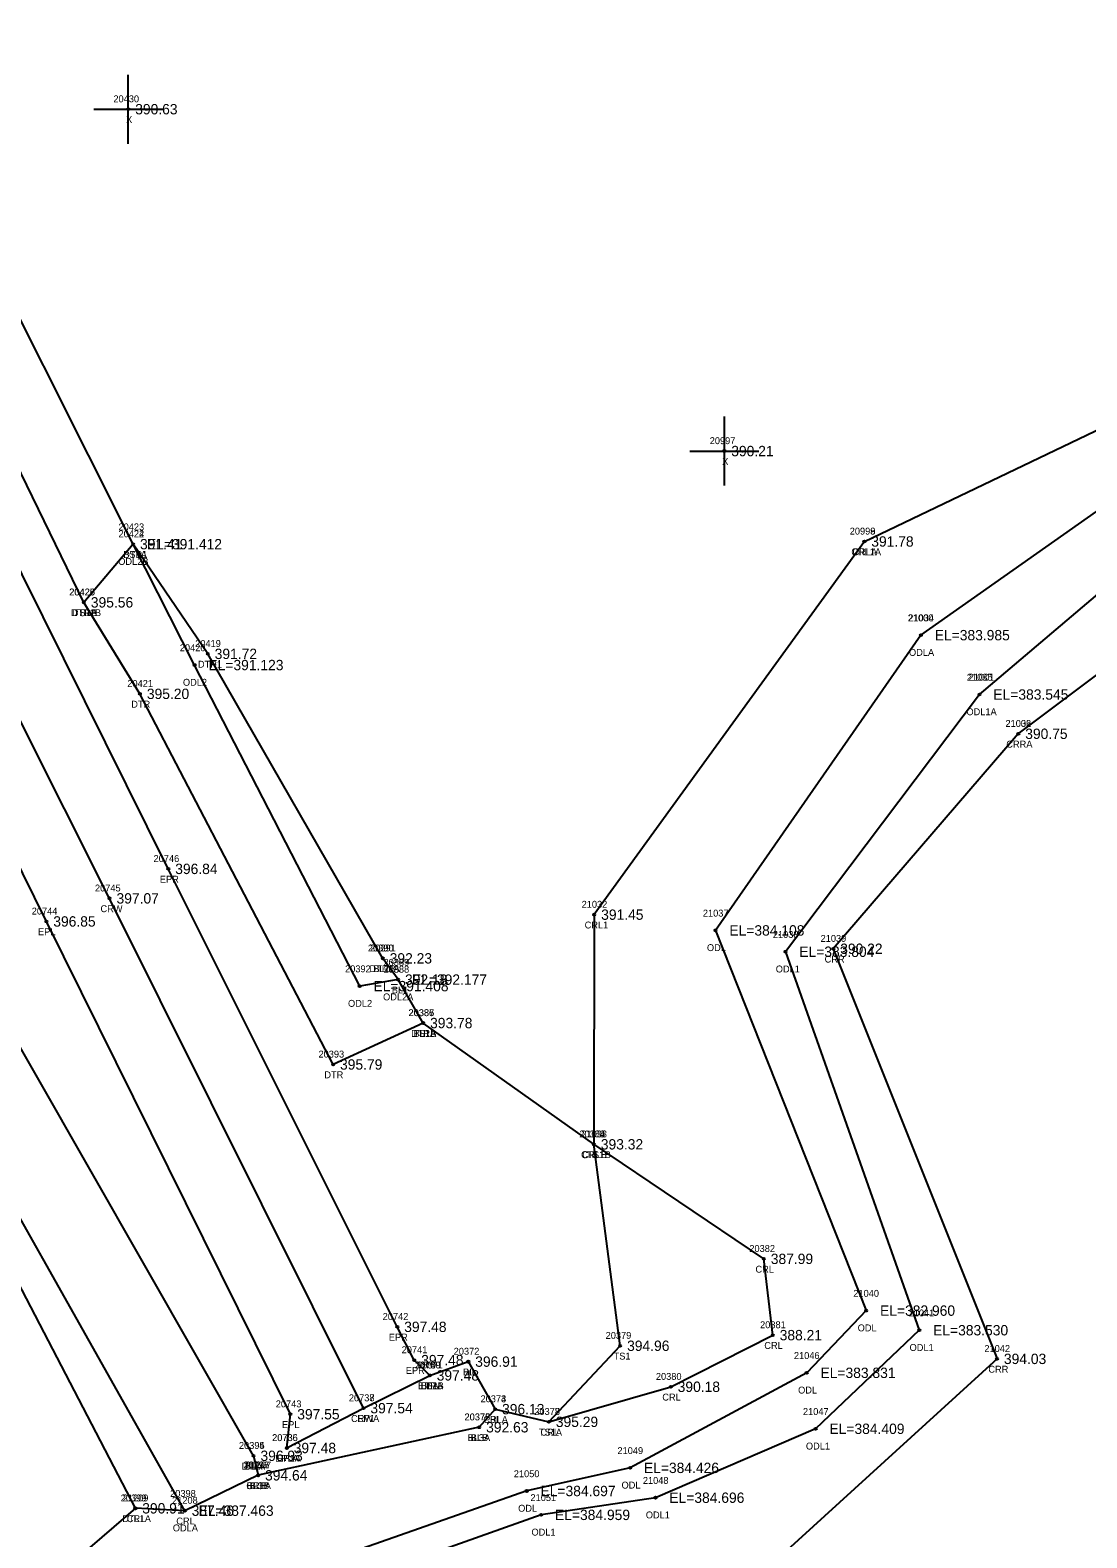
# Model space of a CAD drawing. Extents: x 2186623 to 2187804, y 1079975 to 1082766.
# Drawn here: x 2187375.6 to 2187528.7, y 1081379.4 to 1081597.8 of the extents above; entities that cross this region are included whole.
import ezdxf

# ---------------------------------------------------------------- set-up
doc = ezdxf.new("R2010")
doc.units = 0
for name, color, linetype in [('RD_DTM_BkLn1', 7, 'Continuous'), ('RD_DTM_BkLn2', 7, 'Continuous'), ('RD_DTM_BkLn_txCode', 7, 'Continuous'), ('RD_EX_H2O', 7, 'Continuous'), ('RD_EX_H2O_txCode', 7, 'Continuous'), ('RD_EX_Misc', 7, 'Continuous'), ('RD_EX_Misc_txCode', 7, 'Continuous'), ('RD_EX_Road', 7, 'Continuous'), ('RD_EX_Road_txCode', 7, 'Continuous'), ('RD_EX_TX_H2O_ELEV', 7, 'Continuous'), ('RD_EX_TX_Misc_ELEV', 7, 'Continuous'), ('RD_EX_TX_Road_ELEV', 7, 'Continuous'), ('RD_HC_Survey_ELEV', 7, 'Continuous'), ('RD_HC_Survey_txCode', 7, 'Continuous'), ('RD_SMD_Locator', 7, 'Continuous')]:
    doc.layers.add(name, color=color, linetype=linetype)

msp = doc.modelspace()

# ---------------------------------------------------------------- linework, layer by layer
at = {"layer": 'RD_DTM_BkLn1'}
for p in [(2187440.64, 1081395.41), (2187407.94, 1081391.28)]:
    msp.add_line(p, (2187408.61, 1081388.45), dxfattribs=at)
for points in [[(2187423.87, 1081398.18), (2187387.08, 1081472.03), (2187341.23, 1081563.21), (2187295.24, 1081657.28), (2187251.34, 1081744.68), (2187208.12, 1081834.1), (2187164.51, 1081922.08), (2187120.25, 1082011.57), (2187076.78, 1082099.89), (2187032.8, 1082188.99), (2186987.81, 1082278.27), (2186943.85, 1082367.59), (2186899.96, 1082456.58), (2186856.34, 1082544.86), (2186810.78, 1082636.89), (2186773.78, 1082711.06)], [(2187432.52, 1081453.97), (2187428.89, 1081460.26), (2187426.67, 1081463.34)], [(2187433.48, 1081402.93), (2187439.06, 1081404.92), (2187442.95, 1081398.04), (2187440.64, 1081395.41)]]:
    msp.add_lwpolyline(points, dxfattribs=at)
at = {"layer": 'RD_DTM_BkLn2'}
for points in [[(2187383.36, 1081514.91), (2187356.1, 1081570.87), (2187310.01, 1081662.87), (2187268.1, 1081753.93), (2187240.79, 1081807.4)], [(2187390.49, 1081523.34), (2187364.5, 1081575.03), (2187318.98, 1081666.8), (2187274.04, 1081756.37), (2187249.06, 1081806.96)], [(2187450.74, 1081396.2), (2187461.07, 1081407.22), (2187457.26, 1081436.4), (2187432.52, 1081453.97)]]:
    msp.add_lwpolyline(points, dxfattribs=at)
at = {"layer": 'RD_EX_H2O'}
for points in [[(2187496.45, 1081523.73), (2187533.26, 1081541.33), (2187534.09, 1081589.28), (2187586.73, 1081672.37), (2187607.88, 1081692.4), (2187699.82, 1081817.91)], [(2187504.65, 1081510.16), (2187548.2, 1081540.8), (2187548.57, 1081585.37), (2187590.92, 1081668.52), (2187614.93, 1081686.81), (2187711.24, 1081814.21)], [(2187513.14, 1081501.56), (2187554.74, 1081536.79), (2187555.95, 1081583.38), (2187598.39, 1081664.63), (2187622.08, 1081681.15), (2187720.54, 1081811.18)], [(2187518.76, 1081495.87), (2187564.97, 1081530.52), (2187563.96, 1081581.22), (2187606.37, 1081660.47), (2187630.7, 1081674.32), (2187727, 1081809.08)], [(2187426.67, 1081463.34), (2187401.31, 1081507.45), (2187390.49, 1081523.34), (2187383.36, 1081514.91)], [(2187428.89, 1081460.26), (2187423.32, 1081459.32), (2187399.4, 1081505.83), (2187390.49, 1081523.34)], [(2187496.45, 1081523.73), (2187457.31, 1081469.67), (2187457.26, 1081436.4)], [(2187432.52, 1081453.97), (2187419.47, 1081447.97), (2187391.48, 1081501.66), (2187383.36, 1081514.91)], [(2187504.65, 1081510.16), (2187474.89, 1081467.39), (2187496.72, 1081412.31), (2187488.09, 1081403.3), (2187462.51, 1081389.53), (2187447.52, 1081386.18), (2187416.29, 1081375.24)], [(2187397.97, 1081383.33), (2187356.34, 1081457.17), (2187346.6, 1081488.69), (2187340.91, 1081504.12)], [(2187390.81, 1081383.67), (2187352.92, 1081456.5), (2187343.04, 1081487.06), (2187340.91, 1081504.12)], [(2187407.94, 1081391.28), (2187368.23, 1081460.71), (2187352.45, 1081490.96), (2187351.02, 1081501.64), (2187340.91, 1081504.12)], [(2187513.14, 1081501.56), (2187485.02, 1081464.3), (2187504.41, 1081409.47), (2187489.39, 1081395.19), (2187466.19, 1081385.21), (2187449.62, 1081382.72), (2187418.09, 1081371.52)], [(2187518.76, 1081495.87), (2187491.95, 1081464.73), (2187515.67, 1081405.32), (2187484.66, 1081377.06), (2187475.84, 1081375.83), (2187459.08, 1081366.18)], [(2187442.95, 1081398.04), (2187450.74, 1081396.2), (2187468.4, 1081401.28), (2187483.18, 1081408.76), (2187481.89, 1081419.81), (2187457.26, 1081436.4)], [(2187408.61, 1081388.45), (2187397.97, 1081383.33), (2187390.81, 1081383.67), (2187353.5, 1081351.57), (2187303.78, 1081328.55), (2187200.82, 1081313.95), (2187089.69, 1081253.6), (2186991.97, 1081216.15), (2186919.79, 1081126.27)]]:
    msp.add_lwpolyline(points, dxfattribs=at)
at = {"layer": 'RD_EX_Misc'}
for p, q in [((2187389.79, 1081581.35), (2187389.79, 1081591.35)), ((2187384.79, 1081586.35), (2187394.79, 1081586.35)), ((2187476.16, 1081531.83), (2187476.16, 1081541.83)), ((2187471.16, 1081536.83), (2187481.16, 1081536.83))]:
    msp.add_line(p, q, dxfattribs=at)
at = {"layer": 'RD_EX_Road'}
for points in [[(2187433.48, 1081402.93), (2187431.23, 1081405.14), (2187428.77, 1081409.96), (2187395.59, 1081476.3), (2187350.19, 1081567.64), (2187304.81, 1081661.14), (2187260.59, 1081749.11), (2187216.69, 1081837.7), (2187187.21, 1081897.62), (2187180.39, 1081911.5), (2187172.85, 1081926.68), (2187129.14, 1082015.5), (2187085.24, 1082104.53), (2187041.33, 1082193.41), (2186996.73, 1082282.37), (2186965.72, 1082345.62), (2186953.24, 1082372.4), (2186921.8, 1082435.38), (2186908.96, 1082460.32), (2186865.29, 1082548.82), (2186820.07, 1082641.92), (2186783.9, 1082716)], [(2187412.76, 1081392.41), (2187413.27, 1081397.3), (2187377.92, 1081468.69), (2187333.03, 1081559.63), (2187287.24, 1081651.83), (2187243.42, 1081739.85), (2187221.49, 1081785.01), (2187215.17, 1081798.71), (2187200.07, 1081829.29), (2187156, 1081917.87), (2187111.96, 1082007.49), (2187067.92, 1082095.45), (2187048.95, 1082133.44), (2187040.02, 1082149.93), (2187023.25, 1082184.23), (2186978.93, 1082274.21), (2186935.28, 1082363.16), (2186891.66, 1082452.64), (2186848.32, 1082541.12), (2186802.48, 1082632.77), (2186765.18, 1082707.62)], [(2187412.76, 1081392.41), (2187423.87, 1081398.18), (2187433.48, 1081402.93)]]:
    msp.add_lwpolyline(points, dxfattribs=at)
at = {"layer": 'RD_SMD_Locator'}
for centre in [(2187389.79, 1081586.35), (2187476.16, 1081536.83), (2187390.49, 1081523.34), (2187390.49, 1081523.34), (2187390.49, 1081523.34), (2187496.45, 1081523.73), (2187496.45, 1081523.73), (2187383.36, 1081514.91), (2187383.36, 1081514.91), (2187383.36, 1081514.91), (2187504.65, 1081510.16), (2187504.65, 1081510.16), (2187401.31, 1081507.45), (2187399.4, 1081505.83), (2187391.48, 1081501.66), (2187513.14, 1081501.56), (2187513.14, 1081501.56), (2187518.76, 1081495.87), (2187518.76, 1081495.87), (2187395.59, 1081476.3), (2187387.08, 1081472.03), (2187457.31, 1081469.67), (2187377.92, 1081468.69), (2187474.89, 1081467.39), (2187426.67, 1081463.34), (2187426.67, 1081463.34), (2187485.02, 1081464.3), (2187491.95, 1081464.73), (2187423.32, 1081459.32), (2187428.89, 1081460.26), (2187428.89, 1081460.26), (2187432.52, 1081453.97), (2187432.52, 1081453.97), (2187432.52, 1081453.97), (2187419.47, 1081447.97), (2187457.26, 1081436.4), (2187457.26, 1081436.4), (2187457.26, 1081436.4), (2187481.89, 1081419.81), (2187496.72, 1081412.31), (2187428.77, 1081409.96), (2187483.18, 1081408.76), (2187504.41, 1081409.47), (2187461.07, 1081407.22), (2187431.23, 1081405.14), (2187439.06, 1081404.92), (2187515.67, 1081405.32), (2187433.48, 1081402.93), (2187433.48, 1081402.93), (2187433.48, 1081402.93), (2187488.09, 1081403.3), (2187468.4, 1081401.28), (2187413.27, 1081397.3), (2187423.87, 1081398.18), (2187423.87, 1081398.18), (2187442.95, 1081398.04), (2187442.95, 1081398.04), (2187440.64, 1081395.41), (2187440.64, 1081395.41), (2187450.74, 1081396.2), (2187450.74, 1081396.2), (2187489.39, 1081395.19), (2187407.94, 1081391.28), (2187407.94, 1081391.28), (2187412.76, 1081392.41), (2187412.76, 1081392.41), (2187462.51, 1081389.53), (2187408.61, 1081388.45), (2187408.61, 1081388.45), (2187408.61, 1081388.45), (2187447.52, 1081386.18), (2187466.19, 1081385.21), (2187390.81, 1081383.67), (2187390.81, 1081383.67), (2187397.97, 1081383.33), (2187397.97, 1081383.33), (2187449.62, 1081382.72)]:
    msp.add_circle(centre, 0.15, dxfattribs=at)

# ---------------------------------------------------------------- texts
at = {"layer": 'RD_DTM_BkLn_txCode'}
for s, p in [('20424', (2187388.37, 1081524.34)), ('BS1A', (2187389.06, 1081521.34)), ('20427', (2187381.25, 1081515.91)), ('TS1A', (2187381.91, 1081512.91)), ('20391', (2187424.83, 1081464.34)), ('BL1B', (2187425.27, 1081461.34)), ('20388', (2187426.77, 1081461.26)), ('BL1', (2187427.97, 1081458.26)), ('20385', (2187430.41, 1081454.97)), ('20387', (2187430.41, 1081454.97)), ('TS1B', (2187431.09, 1081451.97)), ('BL1A', (2187431.12, 1081451.97)), ('20384', (2187455.15, 1081437.4)), ('TS1', (2187456.3, 1081434.4)), ('20379', (2187458.96, 1081408.22)), ('20372', (2187436.94, 1081405.92)), ('TS1', (2187460.11, 1081405.22)), ('20371', (2187431.64, 1081403.93)), ('BLA', (2187432.23, 1081400.93)), ('BL', (2187438.3, 1081402.92)), ('20373', (2187440.83, 1081399.04)), ('20378', (2187448.62, 1081397.2)), ('20376', (2187438.5, 1081396.41)), ('20375', (2187438.52, 1081396.41)), ('BL', (2187442.19, 1081396.04)), ('20394', (2187405.82, 1081392.28)), ('BL3A', (2187438.95, 1081393.41)), ('BLB', (2187439.41, 1081393.41)), ('TS1A', (2187449.29, 1081394.2)), ('20396', (2187406.47, 1081389.45)), ('20397', (2187406.49, 1081389.45)), ('BLA', (2187406.69, 1081389.28)), ('BL3B', (2187406.93, 1081386.45)), ('BLB', (2187407.38, 1081386.45))]:
    msp.add_text(s, height=1, dxfattribs=at).set_placement(p)
at = {"layer": 'RD_EX_H2O_txCode'}
for s, p in [('20423', (2187388.37, 1081525.34)), ('20422', (2187388.37, 1081524.34)), ('20998', (2187494.33, 1081524.73)), ('20999', (2187494.33, 1081524.73)), ('DTR1', (2187389.06, 1081521.34)), ('CRL1A', (2187494.56, 1081521.73)), ('CRLA', (2187494.73, 1081521.73)), ('ODL2B', (2187388.33, 1081520.34)), ('20426', (2187381.22, 1081515.91)), ('20425', (2187381.25, 1081515.91)), ('DTR1B', (2187381.46, 1081512.91)), ('DTRB', (2187381.62, 1081512.91)), ('21000', (2187502.74, 1081512.16)), ('21034', (2187502.82, 1081512.16)), ('20420', (2187397.25, 1081507.83)), ('20419', (2187399.48, 1081508.45)), ('ODLA', (2187502.92, 1081507.16)), ('ODLA', (2187502.92, 1081507.16)), ('DTR1', (2187399.88, 1081505.45)), ('21035', (2187511.3, 1081503.56)), ('21001', (2187511.55, 1081503.56)), ('20421', (2187389.65, 1081502.66)), ('ODL2', (2187397.71, 1081502.83)), ('DTR', (2187390.22, 1081499.66)), ('ODL1A', (2187511.24, 1081498.56)), ('ODL1A', (2187511.24, 1081498.56)), ('21002', (2187516.89, 1081496.87)), ('21036', (2187516.9, 1081496.87)), ('CRRA', (2187517.02, 1081493.87)), ('CRRA', (2187517.02, 1081493.87)), ('21032', (2187455.48, 1081470.67)), ('21037', (2187473.05, 1081469.39)), ('CRL1', (2187455.92, 1081467.67)), ('20390', (2187424.51, 1081464.34)), ('ODL', (2187473.64, 1081464.39)), ('21038', (2187483.19, 1081466.3)), ('21039', (2187490.11, 1081465.73)), ('20389', (2187426.77, 1081462.26)), ('CRR', (2187490.69, 1081462.73)), ('20392', (2187421.2, 1081461.32)), ('DTR1A', (2187424.74, 1081461.34)), ('ODL1', (2187483.61, 1081461.3)), ('ODL2', (2187421.63, 1081456.32)), ('ODL2A', (2187426.71, 1081457.26)), ('20386', (2187430.38, 1081454.97)), ('DTRA', (2187430.77, 1081451.97)), ('20393', (2187417.35, 1081448.97)), ('DTR', (2187418.2, 1081445.97)), ('20383', (2187455.15, 1081437.4)), ('21033', (2187455.43, 1081437.4)), ('CRL1B', (2187455.4, 1081434.4)), ('CRLB', (2187455.56, 1081434.4)), ('20382', (2187479.78, 1081420.81)), ('CRL', (2187480.67, 1081417.81)), ('21040', (2187494.85, 1081414.31)), ('20381', (2187481.34, 1081409.76)), ('21041', (2187502.86, 1081411.47)), ('ODL', (2187495.48, 1081409.31)), ('CRL', (2187481.95, 1081406.76)), ('21046', (2187486.24, 1081405.3)), ('ODL1', (2187503, 1081406.47)), ('21042', (2187513.84, 1081406.32)), ('CRR', (2187514.42, 1081403.32)), ('20380', (2187466.24, 1081402.28)), ('20374', (2187440.83, 1081399.04)), ('CRL', (2187467.17, 1081399.28)), ('ODL', (2187486.85, 1081400.3)), ('20377', (2187448.62, 1081397.2)), ('21047', (2187487.55, 1081397.19)), ('CRLA', (2187441.23, 1081396.04)), ('20395', (2187405.82, 1081392.28)), ('CRL', (2187449.51, 1081394.2)), ('ODL1', (2187487.98, 1081392.19)), ('21049', (2187460.67, 1081391.53)), ('DTLA', (2187406.21, 1081389.28)), ('21207', (2187406.77, 1081389.45)), ('21050', (2187445.65, 1081388.18)), ('CRLA', (2187406.89, 1081386.45)), ('ODL', (2187461.26, 1081386.53)), ('21048', (2187464.35, 1081387.21)), ('20399', (2187388.69, 1081384.67)), ('21209', (2187388.98, 1081384.67)), ('20398', (2187395.85, 1081385.33)), ('21208', (2187396.13, 1081384.33)), ('21051', (2187448.07, 1081384.72)), ('DTL1A', (2187388.91, 1081381.67)), ('CRL', (2187389.58, 1081381.67)), ('CRL', (2187396.74, 1081381.33)), ('ODL', (2187446.28, 1081383.18)), ('ODL1', (2187464.78, 1081382.21)), ('ODLA', (2187396.24, 1081380.33)), ('ODL1', (2187448.21, 1081379.72))]:
    msp.add_text(s, height=1, dxfattribs=at).set_placement(p)
at = {"layer": 'RD_EX_Misc_txCode'}
for s, p in [('20430', (2187387.63, 1081587.35)), ('X', (2187389.47, 1081584.35)), ('20997', (2187474.04, 1081537.83)), ('X', (2187475.85, 1081534.83))]:
    msp.add_text(s, height=1, dxfattribs=at).set_placement(p)
at = {"layer": 'RD_EX_Road_txCode'}
for s, p in [('20746', (2187393.45, 1081477.3)), ('EPR', (2187394.36, 1081474.3)), ('20744', (2187375.8, 1081469.69)), ('EPL', (2187376.71, 1081466.69)), ('20742', (2187426.65, 1081410.96)), ('EPR', (2187427.54, 1081407.96)), ('20741', (2187429.4, 1081406.14)), ('EPR', (2187430, 1081403.14)), ('20740', (2187431.32, 1081403.93)), ('20739', (2187431.36, 1081403.93)), ('EPRA', (2187431.76, 1081400.93)), ('EP1B', (2187432.08, 1081400.93)), ('20737', (2187421.75, 1081399.18)), ('20743', (2187411.16, 1081398.3)), ('EPL', (2187412.07, 1081395.3)), ('EP1', (2187422.95, 1081396.18)), ('20736', (2187410.62, 1081393.41)), ('20735', (2187410.64, 1081393.41)), ('EPLA', (2187411.07, 1081390.41)), ('EP1A', (2187411.35, 1081390.41))]:
    msp.add_text(s, height=1, dxfattribs=at).set_placement(p)
at = {"layer": 'RD_EX_TX_H2O_ELEV'}
for s, p in [('391.41', (2187391.49, 1081522.59)), ('EL=391.412', (2187392.49, 1081522.59)), ('391.78', (2187497.45, 1081522.98)), ('391.78', (2187497.45, 1081522.98)), ('395.56', (2187384.36, 1081514.16)), ('395.56', (2187384.36, 1081514.16)), ('EL=383.985', (2187506.65, 1081509.41)), ('EL=383.985', (2187506.65, 1081509.41)), ('391.72', (2187402.31, 1081506.7)), ('EL=391.123', (2187401.4, 1081505.08)), ('395.20', (2187392.48, 1081500.91)), ('EL=383.545', (2187515.14, 1081500.81)), ('EL=383.545', (2187515.14, 1081500.81)), ('390.75', (2187519.76, 1081495.12)), ('390.75', (2187519.76, 1081495.12)), ('391.45', (2187458.31, 1081468.92)), ('EL=384.108', (2187476.89, 1081466.64)), ('390.22', (2187492.95, 1081463.98)), ('392.23', (2187427.67, 1081462.59)), ('EL=383.804', (2187487.02, 1081463.55)), ('EL=392.177', (2187430.89, 1081459.51)), ('EL=391.408', (2187425.32, 1081458.57)), ('393.78', (2187433.52, 1081453.22)), ('395.79', (2187420.47, 1081447.22)), ('393.32', (2187458.26, 1081435.65)), ('393.32', (2187458.26, 1081435.65)), ('387.99', (2187482.89, 1081419.06)), ('EL=382.960', (2187498.72, 1081411.56)), ('388.21', (2187484.18, 1081408.01)), ('EL=383.530', (2187506.41, 1081408.72)), ('EL=383.831', (2187490.09, 1081402.55)), ('394.03', (2187516.67, 1081404.57)), ('390.18', (2187469.4, 1081400.53)), ('396.13', (2187443.95, 1081397.29)), ('395.29', (2187451.74, 1081395.45)), ('EL=384.409', (2187491.39, 1081394.44)), ('396.93', (2187408.94, 1081390.53)), ('394.64', (2187409.61, 1081387.7)), ('EL=384.426', (2187464.51, 1081388.78)), ('EL=384.697', (2187449.52, 1081385.43)), ('390.91', (2187391.81, 1081382.92)), ('390.91', (2187391.81, 1081382.92)), ('EL=384.696', (2187468.19, 1081384.46)), ('387.46', (2187398.97, 1081382.58)), ('EL=387.463', (2187399.97, 1081382.58)), ('EL=384.959', (2187451.62, 1081381.97))]:
    msp.add_text(s, height=1.5, dxfattribs=at).set_placement(p)
at = {"layer": 'RD_EX_TX_Misc_ELEV'}
for s, p in [('390.63', (2187390.79, 1081585.6)), ('390.21', (2187477.16, 1081536.08)), ('391.41', (2187391.49, 1081522.59)), ('395.56', (2187384.36, 1081514.16)), ('392.23', (2187427.67, 1081462.59)), ('392.18', (2187429.89, 1081459.51)), ('393.78', (2187433.52, 1081453.22)), ('393.78', (2187433.52, 1081453.22)), ('393.32', (2187458.26, 1081435.65)), ('394.96', (2187462.07, 1081406.47)), ('396.91', (2187440.06, 1081404.17)), ('397.48', (2187434.48, 1081402.18)), ('396.13', (2187443.95, 1081397.29)), ('392.63', (2187441.64, 1081394.66)), ('392.63', (2187441.64, 1081394.66)), ('395.29', (2187451.74, 1081395.45)), ('396.93', (2187408.94, 1081390.53)), ('394.64', (2187409.61, 1081387.7)), ('394.64', (2187409.61, 1081387.7))]:
    msp.add_text(s, height=1.5, dxfattribs=at).set_placement(p)
at = {"layer": 'RD_EX_TX_Road_ELEV'}
for s, p in [('396.84', (2187396.59, 1081475.55)), ('396.85', (2187378.92, 1081467.94)), ('397.48', (2187429.77, 1081409.21)), ('397.48', (2187432.23, 1081404.39)), ('397.48', (2187434.48, 1081402.18)), ('397.48', (2187434.48, 1081402.18)), ('397.55', (2187414.27, 1081396.55)), ('397.54', (2187424.87, 1081397.43)), ('397.48', (2187413.76, 1081391.66)), ('397.48', (2187413.76, 1081391.66))]:
    msp.add_text(s, height=1.5, dxfattribs=at).set_placement(p)
at = {"layer": 'RD_HC_Survey_ELEV'}
for s, p in [('397.07', (2187388.08, 1081471.28)), ('397.54', (2187424.87, 1081397.43))]:
    msp.add_text(s, height=1.5, dxfattribs=at).set_placement(p)
at = {"layer": 'RD_HC_Survey_txCode'}
for s, p in [('20745', (2187384.96, 1081473.03)), ('CRW', (2187385.76, 1081470.03)), ('20738', (2187421.75, 1081399.18)), ('CRWA', (2187422.07, 1081396.18))]:
    msp.add_text(s, height=1, dxfattribs=at).set_placement(p)

doc.saveas('drawing.dxf')
